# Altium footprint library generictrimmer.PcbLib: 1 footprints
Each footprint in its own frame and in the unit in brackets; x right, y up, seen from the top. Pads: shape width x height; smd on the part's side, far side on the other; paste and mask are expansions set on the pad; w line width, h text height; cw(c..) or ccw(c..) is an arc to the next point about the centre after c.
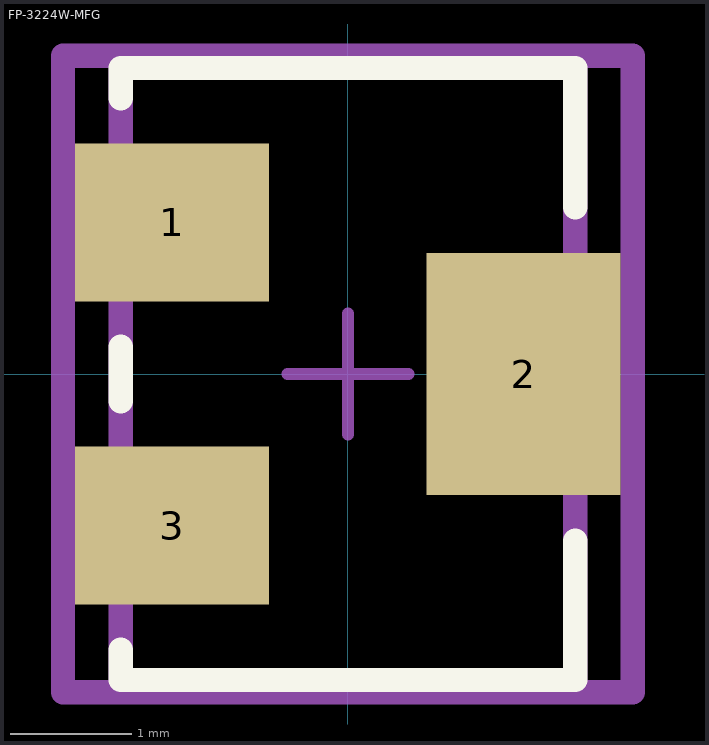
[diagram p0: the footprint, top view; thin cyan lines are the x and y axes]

## FP-3224W-MFG [mm]
pads (3):
  rect 1.6x1.3 smd paste+0 mask+0: 1(-1.45,1.25) 3(-1.45,-1.25)
  rect 1.6x2 smd paste+0 mask+0: 2(1.45,0)
Top Overlay:
  lines w0.2: -1.875,-2.275 -1.875,-2.525 1.875,-2.525 1.875,-1.375 ; -1.875,-0.225 -1.875,0.225 ; -1.875,2.275 -1.875,2.525 1.875,2.525 1.875,1.375
Top Assembly:
  lines w0.2: -2.35,-2.625 -2.35,2.625 2.35,2.625 2.35,-2.625 -2.35,-2.625
  text ".Designator" at 0,-0.001 h1
Top 3D Body:
  lines w0.2: -1.875,-2.525 -1.875,2.525 1.875,2.525 1.875,-2.525 -1.875,-2.525
Top Courtyard:
  lines w0.2: -2.35,-2.625 -2.35,2.625 2.35,2.625 2.35,-2.625 -2.35,-2.625
Top Component Center:
  lines w0.1: -0.5,0 0.5,0 ; 0,-0.5 0,0.5
3D body "Res_Bourns_3224W-1-103E_eec.STEP": height 0.25, standoff 0, extent -2.35,-2.625 2.35,2.625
